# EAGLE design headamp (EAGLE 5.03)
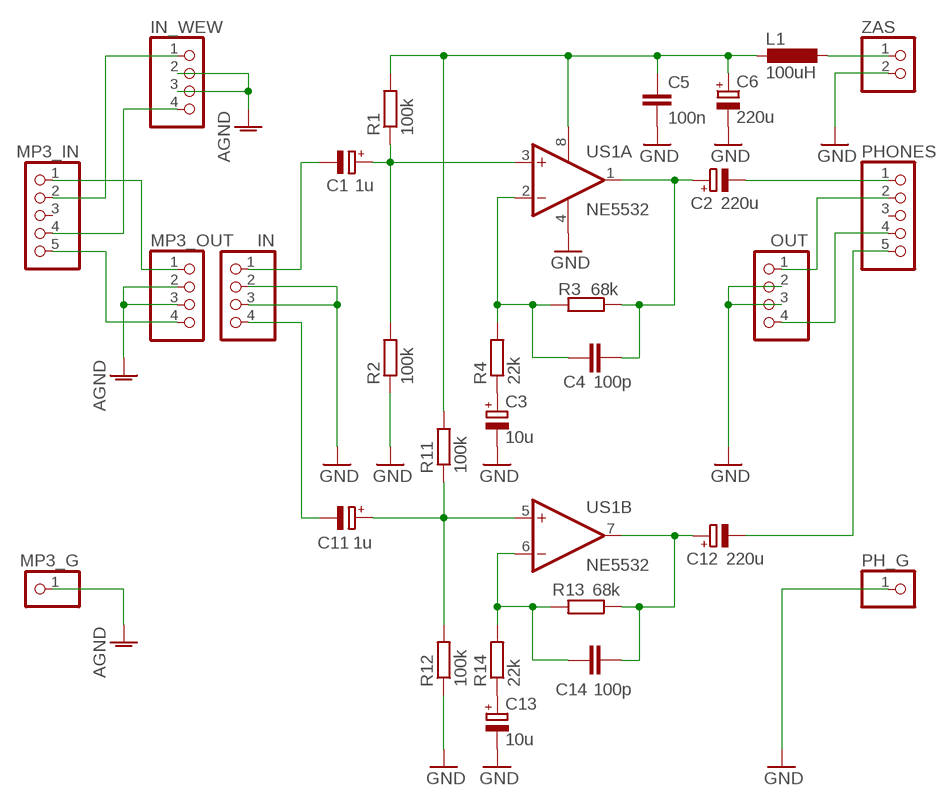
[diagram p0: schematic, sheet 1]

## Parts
C1  1u  CPOL-EUE2.5-5  [E2,5-5]
C2  220u  CPOL-EUE5-8.5  [E5-8,5]
C3  10u  CPOL-EUE2.5-6  [E2,5-6]
C4  100p  C-EU025-025X050  [C025-025X050]
C5  100n  C-EU025-025X050  [C025-025X050]
C6  220u  CPOL-EUE5-8.5  [E5-8,5]
C11  1u  CPOL-EUE2.5-5  [E2,5-5]
C12  220u  CPOL-EUE5-8.5  [E5-8,5]
C13  10u  CPOL-EUE2.5-6  [E2,5-6]
C14  100p  C-EU025-025X050  [C025-025X050]
IN  PINHD-1X4  [1X04]
IN_WEW  PINHD-1X4  [1X04]
L1  100uH  L-EU0204/7  [0204/7]
MP3_G  PINHD-1X1  [1X01]
MP3_IN  PINHD-1X5  [1X05]
MP3_OUT  PINHD-1X4  [1X04]
OUT  PINHD-1X4  [1X04]
PH_G  PINHD-1X1  [1X01]
PHONES  PINHD-1X5  [1X05]
R1  100k  R-EU_0207/10  [0207/10]
R2  100k  R-EU_0207/10  [0207/10]
R3  68k  R-EU_0207/10  [0207/10]
R4  22k  R-EU_0207/10  [0207/10]
R11  100k  R-EU_0207/10  [0207/10]
R12  100k  R-EU_0207/10  [0207/10]
R13  68k  R-EU_0207/10  [0207/10]
R14  22k  R-EU_0207/10  [0207/10]
US1  NE5532  NE5532N  [DIL08]
ZAS  PINHD-1X2  [1X02]

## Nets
AGND: IN_WEW.2 IN_WEW.3 MP3_G.1 MP3_OUT.2 MP3_OUT.3
GND: C3.- C5.2 C6.- C13.- IN.2 IN.3 OUT.2 OUT.3 PH_G.1 R2.1 R12.1 US1.4(P:V-) ZAS.2
N$1: C1.- IN.1
N$2: C4.1 R3.2 R4.2 US1.2(A:-IN)
N$3: C1.+ R1.1 R2.2 US1.3(A:+IN)
N$4: C2.+ C4.2 R3.1 US1.1(A:OUT)
N$5: C5.1 C6.+ L1.2 R1.2 R11.2 US1.8(P:V+)
N$6: C3.+ R4.1
N$7: C2.- PHONES.1
N$8: OUT.1 PHONES.2
N$9: C11.- IN.4
N$10: C11.+ R11.1 R12.2 US1.5(B:+IN)
N$11: C12.+ C14.2 R13.1 US1.7(B:OUT)
N$12: C14.1 R13.2 R14.2 US1.6(B:-IN)
N$13: C13.+ R14.1
N$14: OUT.4 PHONES.4
N$15: C12.- PHONES.5
N$16: MP3_IN.1 MP3_OUT.1
N$17: MP3_IN.5 MP3_OUT.4
N$18: IN_WEW.1 MP3_IN.2
N$19: IN_WEW.4 MP3_IN.4
N$20: L1.1 ZAS.1
Unconnected: MP3_IN.3 PHONES.3

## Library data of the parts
C1-C3 C6 C11-C13 = rcl:CPOL-EU: POLARIZED CAPACITOR, European symbol
C4 C5 C14 = rcl:C-EU: CAPACITOR, European symbol
IN IN_WEW MP3_OUT OUT = pinhead:PINHD-1X4: PIN HEADER
L1 = rcl:L-EU: INDUCTOR, European symbol
MP3_G PH_G = pinhead:PINHD-1X1: PIN HEADER
MP3_IN PHONES = pinhead:PINHD-1X5: PIN HEADER
R1-R4 R11-R14 = rcl:R-EU_: RESISTOR, European symbol
US1 = linear:NE5532: AUDIO AMPLIFIER
ZAS = pinhead:PINHD-1X2: PIN HEADER

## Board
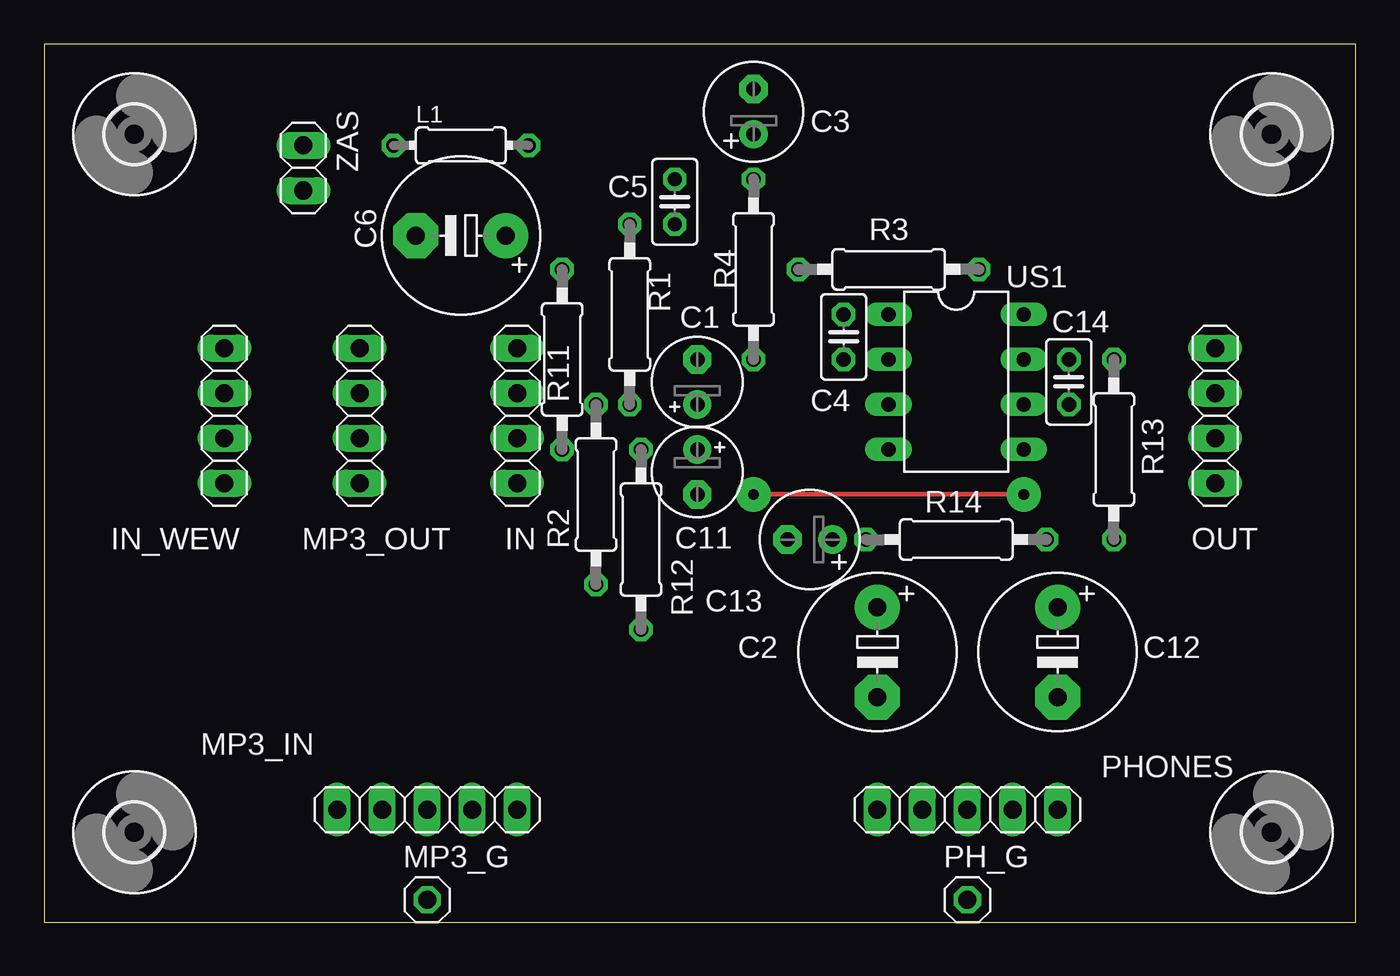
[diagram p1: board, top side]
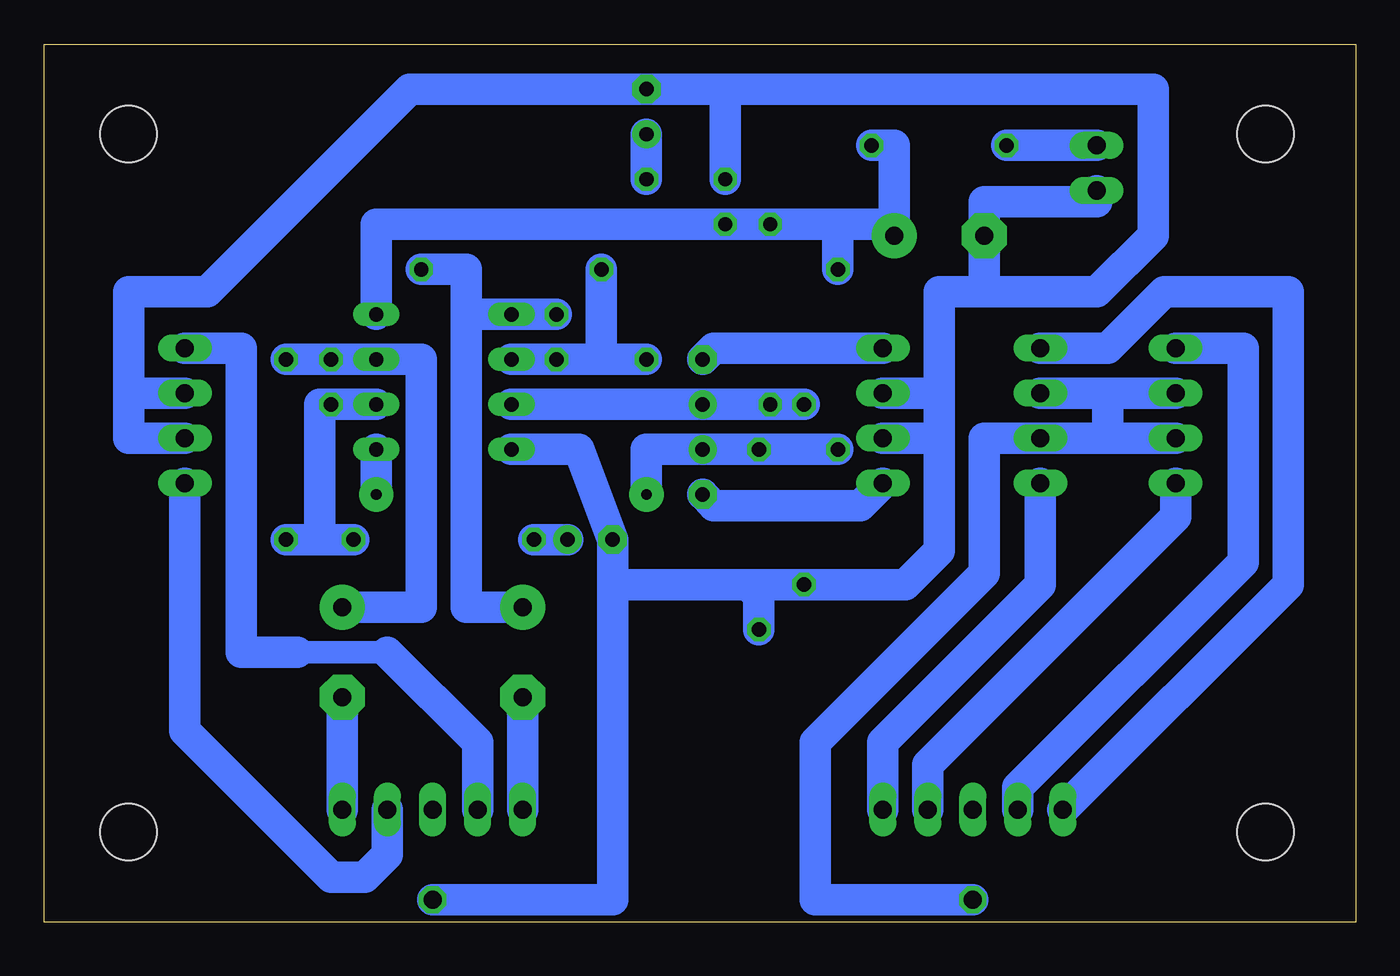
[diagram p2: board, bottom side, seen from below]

Size 73.97 x 49.52 mm. Coordinates in mm from the lower left corner, seen from the top.
Outline: 0,0 73.97,0 73.97,49.52 0,49.52 0,0
Copper layers (1*16): Top 0.035mm / dielectric 1.5mm / Bottom 0.035mm
Design rules "default": minimum track width 10mil, minimum drill 24mil, track to track 8mil, track to pad 8mil, pad to pad 8mil, via to via 8mil, smd to smd 8mil, copper to edge 40mil, drill to drill 8mil, minimum pad ring 10mil, minimum via ring 8mil, stop-mask expansion 4mil, vias tented up to drill 0mil, thermal gap 10mil

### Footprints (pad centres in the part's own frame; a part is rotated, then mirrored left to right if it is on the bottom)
E2,5-5 = drill 0.813 pad 1.6 round: + -1.27,0 | drill 0.813 pad 1.6 octagon: - 1.27,0
E5-8,5 = drill 1.016 pad 2.54 round: + -2.54,0 | drill 1.016 pad 2.54 octagon: - 2.54,0
E2,5-6 = drill 0.813 pad 1.6 round: + -1.27,0 | drill 0.813 pad 1.6 octagon: - 1.27,0
C025-025X050 = drill 0.813 octagon: 1 -1.27,0; 2 1.27,0
1X04 = drill 1.016 long: 1 -3.81,0; 2 -1.27,0; 3 1.27,0; 4 3.81,0
0204/7 = drill 0.813 octagon: 1 -3.81,0; 2 3.81,0
1X01 = drill 1.016 octagon: 1 0,0
1X05 = drill 1.016 long: 1 -5.08,0; 2 -2.54,0; 3 0,0; 4 2.54,0; 5 5.08,0
0207/10 = drill 0.813 octagon: 1 -5.08,0; 2 5.08,0
3,2 = hole 3.2: 0,0
DIL08 = drill 0.813 long: 1 -3.81,-3.81; 2 -1.27,-3.81; 3 1.27,-3.81; 4 3.81,-3.81; 5 3.81,3.81; 6 1.27,3.81; 7 -1.27,3.81; 8 -3.81,3.81
1X02 = drill 1.016 long: 1 -1.27,0; 2 1.27,0

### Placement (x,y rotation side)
C1  36.83,30.48 90 top
C2  46.99,15.24 270 top
C3  40.01,45.72 90 top
C4  45.09,33.02 90 top
C5  35.56,40.64 90 top
C6  23.5,38.73 180 top
C11  36.83,25.4 270 top
C12  57.15,15.24 270 top
C13  43.18,21.59 180 top
C14  57.78,30.48 90 top
IN  26.67,28.57 270 top
IN_WEW  10.16,28.57 270 top
L1  23.5,43.81 0 top
MP3_G  21.59,1.27 0 top
MP3_IN  21.59,6.35 0 top
MP3_OUT  17.78,28.57 270 top
OUT  66.04,28.57 270 top
PH_G  52.07,1.27 0 top
PHONES  52.07,6.35 0 top
R1  33.02,34.29 90 top
R2  31.11,24.13 90 top
R3  47.62,36.83 180 top
R4  40.01,36.83 270 top
R11  29.21,31.75 90 top
R12  33.66,21.59 90 top
R13  60.33,26.67 270 top
R14  51.44,21.59 0 top
U$1  [3,2]  5.08,44.45 0 top
U$2  [3,2]  69.22,44.45 0 top
U$3  [3,2]  69.22,5.08 0 top
U$4  [3,2]  5.08,5.08 0 top
US1  51.44,30.48 270 top
ZAS  14.61,42.55 270 top

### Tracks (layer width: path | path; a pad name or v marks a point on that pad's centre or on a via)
AGND
  Bottom 1.778: 13.97,27.3 IN_WEW.3 | 13.97,27.3 13.97,29.84 | 13.97,29.84 IN_WEW.2 | 13.97,29.84 MP3_OUT.2 | 13.97,27.3 MP3_OUT.3 20.95,27.3 20.95,19.68 30.48,10.16 30.48,1.27 MP3_G.1
GND
  Bottom 1.778: US1.4 43.81,26.67 C13.- 41.91,19.05 | 41.91,19.05 41.91,1.27 PH_G.1 | 41.91,19.05 34.29,19.05 | 34.29,19.05 R2.1 25.4,19.05 23.5,20.95 23.5,27.3 | R12.1 33.66,18.41 34.29,19.05 | 23.5,27.3 23.5,29.84 | 23.5,29.84 IN.2 | 23.5,27.3 IN.3 | 69.22,27.3 69.22,29.84 OUT.2 | 69.22,27.3 OUT.3 | 69.22,27.3 69.22,35.56 64.77,35.56 53.34,46.99 C3.- 35.56,46.99 | 35.56,46.99 C5.2 | ZAS.2 14.61,40.64 20.95,40.64 C6.- 20.95,35.56 23.5,35.56 | 35.56,46.99 11.43,46.99 11.43,38.73 14.61,35.56 23.5,35.56 | 23.5,29.84 23.5,35.56
N$1
  Bottom 1.778: IN.1 36.2,32.38 C1.-
N$2
  Bottom 1.778: 42.55,31.75 R3.2 | 42.55,31.75 C4.1 US1.2 | R4.2 42.55,31.75
N$3
  Bottom 1.778: US1.3 C1.+ R1.1 R2.2
N$4
  Bottom 1.778: 45.72,34.29 US1.1 | C2.+ 50.16,17.78 50.16,34.29 | 50.16,34.29 45.72,34.29 | 45.72,34.29 C4.2 | R3.1 50.16,36.83 50.16,34.29
N$5
  Bottom 1.778: US1.8 55.24,39.37 C5.1 | R1.2 C5.1 | 29.21,39.37 R1.2 | 29.21,39.37 R11.2 | R1.2 C5.1 | 29.21,39.37 26.67,39.37 C6.+ 26.04,43.81 L1.2
N$6
  Bottom 1.778: R4.1 C3.+
N$7
  Bottom 1.778: PHONES.1 C2.-
N$8
  Bottom 1.27: 54.61,15.24 59.69,15.24
  Bottom 1.778: PHONES.2 49.53,10.16 54.61,15.24 | OUT.1 62.87,32.38 62.87,15.24 59.69,15.24
N$9
  Bottom 1.778: C11.- 36.2,23.5 27.94,23.5 IN.4
N$10  (via drill 0.6 pad 1.93)
  Top 0.254: v40.01,24.13 v55.24,24.13
  Bottom 1.778: R11.1 R12.2 C11.+ 40.01,26.67 v40.01,24.13 | v55.24,24.13 US1.5
N$11
  Bottom 1.778: 54.61,31.75 US1.7 | 54.61,31.75 C14.2 R13.1 | C12.+ 52.7,17.78 52.7,31.75 54.61,31.75
N$12
  Bottom 1.778: US1.6 C14.1 58.42,29.21 58.42,21.59 | R14.2 58.42,21.59 | 58.42,21.59 R13.2
N$13
  Bottom 1.778: C13.+ R14.1
N$14
  Bottom 1.778: PHONES.4 54.61,3.81 55.88,2.54 57.78,2.54 66.04,10.79 OUT.4
N$15
  Bottom 1.778: PHONES.5 C12.-
N$16
  Bottom 1.778: MP3_IN.1 3.81,19.05 3.81,35.56 10.79,35.56 13.97,32.38 MP3_OUT.1
N$17
  Bottom 1.778: MP3_IN.5 26.67,10.16 17.78,19.05 MP3_OUT.4
N$18
  Bottom 1.778: MP3_IN.2 19.05,7.62 6.35,20.32 6.35,32.38 IN_WEW.1
N$19
  Bottom 1.778: MP3_IN.4 24.13,8.89 10.16,22.86 IN_WEW.4
N$20
  Bottom 1.778: L1.1 17.78,43.81 17.14,43.81 ZAS.1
